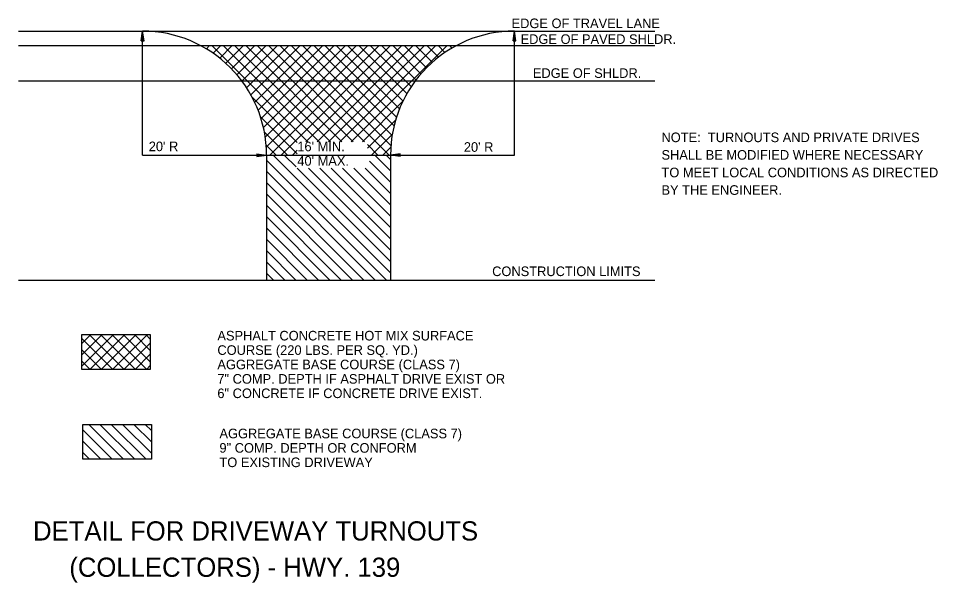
# Model space of a CAD drawing. Extents: x 1955770 to 1955917, y 566446 to 566544.
# Drawn here: x 1955775.3 to 1955832.8, y 566506.6 to 566541.9 of the extents above; entities that cross this region are included whole.
import ezdxf

# ---------------------------------------------------------------- set-up
doc = ezdxf.new("R2010")
doc.units = 0
for name, color, linetype in [('Default', 7, 'Continuous'), ('R_Grid', 7, 'Continuous'), ('R_Logo', 7, 'Continuous')]:
    doc.layers.add(name, color=color, linetype=linetype)

msp = doc.modelspace()

# ---------------------------------------------------------------- linework, layer by layer
at = {"layer": 'R_Grid'}
for p, q in [((1955782.989, 566540.478), (1955783.079, 566541.078)), ((1955782.989, 566540.478), (1955783.079, 566541.078)), ((1955783.169, 566540.478), (1955783.079, 566541.078)), ((1955783.169, 566540.478), (1955783.079, 566541.078)), ((1955806.234, 566540.478), (1955806.324, 566541.078)), ((1955806.234, 566540.478), (1955806.324, 566541.078)), ((1955806.414, 566540.478), (1955806.324, 566541.078)), ((1955806.414, 566540.478), (1955806.324, 566541.078)), ((1955782.989, 566540.478), (1955783.169, 566540.478)), ((1955782.989, 566540.478), (1955783.169, 566540.478)), ((1955783.004, 566540.478), (1955783.079, 566540.978)), ((1955783.004, 566540.478), (1955783.079, 566540.978)), ((1955783.019, 566540.478), (1955783.079, 566540.875)), ((1955783.019, 566540.478), (1955783.079, 566540.875)), ((1955783.034, 566540.478), (1955783.079, 566540.775)), ((1955783.034, 566540.478), (1955783.079, 566540.775)), ((1955783.05, 566540.478), (1955783.079, 566540.673)), ((1955783.05, 566540.478), (1955783.079, 566540.673)), ((1955783.065, 566540.478), (1955783.079, 566540.573)), ((1955783.065, 566540.478), (1955783.079, 566540.573)), ((1955783.154, 566540.478), (1955783.079, 566540.978)), ((1955783.154, 566540.478), (1955783.079, 566540.978)), ((1955783.139, 566540.478), (1955783.079, 566540.875)), ((1955783.139, 566540.478), (1955783.079, 566540.875)), ((1955783.124, 566540.478), (1955783.079, 566540.775)), ((1955783.124, 566540.478), (1955783.079, 566540.775)), ((1955783.109, 566540.478), (1955783.079, 566540.673)), ((1955783.109, 566540.478), (1955783.079, 566540.673)), ((1955783.093, 566540.478), (1955783.079, 566540.573)), ((1955783.093, 566540.478), (1955783.079, 566540.573)), ((1955806.234, 566540.478), (1955806.414, 566540.478)), ((1955806.234, 566540.478), (1955806.414, 566540.478)), ((1955806.249, 566540.478), (1955806.324, 566540.978)), ((1955806.249, 566540.478), (1955806.324, 566540.978)), ((1955806.265, 566540.478), (1955806.324, 566540.875)), ((1955806.265, 566540.478), (1955806.324, 566540.875)), ((1955806.28, 566540.478), (1955806.324, 566540.775)), ((1955806.28, 566540.478), (1955806.324, 566540.775)), ((1955806.295, 566540.478), (1955806.324, 566540.673)), ((1955806.295, 566540.478), (1955806.324, 566540.673)), ((1955806.31, 566540.478), (1955806.324, 566540.573)), ((1955806.31, 566540.478), (1955806.324, 566540.573)), ((1955806.399, 566540.478), (1955806.324, 566540.978)), ((1955806.399, 566540.478), (1955806.324, 566540.978)), ((1955806.384, 566540.478), (1955806.324, 566540.875)), ((1955806.384, 566540.478), (1955806.324, 566540.875)), ((1955806.369, 566540.478), (1955806.324, 566540.775)), ((1955806.369, 566540.478), (1955806.324, 566540.775)), ((1955806.354, 566540.478), (1955806.324, 566540.673)), ((1955806.354, 566540.478), (1955806.324, 566540.673)), ((1955806.338, 566540.478), (1955806.324, 566540.573)), ((1955806.338, 566540.478), (1955806.324, 566540.573)), ((1955790.228, 566533.42), (1955790.828, 566533.33)), ((1955790.228, 566533.42), (1955790.228, 566533.24)), ((1955790.228, 566533.42), (1955790.828, 566533.33)), ((1955790.228, 566533.42), (1955790.228, 566533.24)), ((1955790.228, 566533.405), (1955790.727, 566533.33)), ((1955790.228, 566533.405), (1955790.727, 566533.33)), ((1955790.228, 566533.39), (1955790.624, 566533.33)), ((1955790.228, 566533.39), (1955790.624, 566533.33)), ((1955790.228, 566533.375), (1955790.524, 566533.33)), ((1955790.228, 566533.375), (1955790.524, 566533.33)), ((1955790.228, 566533.359), (1955790.423, 566533.33)), ((1955790.228, 566533.359), (1955790.423, 566533.33)), ((1955790.228, 566533.344), (1955790.322, 566533.33)), ((1955790.228, 566533.344), (1955790.322, 566533.33)), ((1955790.228, 566533.24), (1955790.828, 566533.33)), ((1955790.228, 566533.301), (1955790.423, 566533.33)), ((1955790.228, 566533.27), (1955790.624, 566533.33)), ((1955790.228, 566533.255), (1955790.727, 566533.33)), ((1955790.228, 566533.285), (1955790.524, 566533.33)), ((1955790.228, 566533.316), (1955790.322, 566533.33)), ((1955790.228, 566533.24), (1955790.828, 566533.33)), ((1955790.228, 566533.301), (1955790.423, 566533.33)), ((1955790.228, 566533.27), (1955790.624, 566533.33)), ((1955790.228, 566533.255), (1955790.727, 566533.33)), ((1955790.228, 566533.285), (1955790.524, 566533.33)), ((1955790.228, 566533.316), (1955790.322, 566533.33)), ((1955799.176, 566533.42), (1955798.576, 566533.33)), ((1955799.176, 566533.42), (1955798.576, 566533.33)), ((1955799.176, 566533.24), (1955798.576, 566533.33)), ((1955799.176, 566533.24), (1955798.576, 566533.33)), ((1955799.176, 566533.405), (1955798.676, 566533.33)), ((1955799.176, 566533.405), (1955798.676, 566533.33)), ((1955799.176, 566533.255), (1955798.676, 566533.33)), ((1955799.176, 566533.255), (1955798.676, 566533.33)), ((1955799.176, 566533.39), (1955798.779, 566533.33)), ((1955799.176, 566533.39), (1955798.779, 566533.33)), ((1955799.176, 566533.27), (1955798.779, 566533.33)), ((1955799.176, 566533.27), (1955798.779, 566533.33)), ((1955799.176, 566533.375), (1955798.879, 566533.33)), ((1955799.176, 566533.375), (1955798.879, 566533.33)), ((1955799.176, 566533.285), (1955798.879, 566533.33)), ((1955799.176, 566533.285), (1955798.879, 566533.33)), ((1955799.176, 566533.359), (1955798.981, 566533.33)), ((1955799.176, 566533.359), (1955798.981, 566533.33)), ((1955799.176, 566533.301), (1955798.981, 566533.33)), ((1955799.176, 566533.301), (1955798.981, 566533.33)), ((1955799.176, 566533.344), (1955799.081, 566533.33)), ((1955799.176, 566533.344), (1955799.081, 566533.33)), ((1955799.176, 566533.316), (1955799.081, 566533.33)), ((1955799.176, 566533.316), (1955799.081, 566533.33)), ((1955799.176, 566533.24), (1955799.176, 566533.42)), ((1955799.176, 566533.24), (1955799.176, 566533.42))]:
    msp.add_line(p, q, dxfattribs=at)
at = {"layer": 'R_Logo'}
for p, q in [((1955775.318, 566541.078), (1955815.092, 566541.078)), ((1955783.079, 566533.33), (1955783.079, 566541.078)), ((1955806.324, 566533.33), (1955806.324, 566541.078)), ((1955775.318, 566540.176), (1955815.092, 566540.176)), ((1955787.066, 566539.974), (1955787.268, 566540.176)), ((1955787.41, 566540.176), (1955793.415, 566534.171)), ((1955787.495, 566539.697), (1955787.975, 566540.176)), ((1955787.901, 566539.395), (1955788.682, 566540.176)), ((1955788.117, 566540.176), (1955794.122, 566534.171)), ((1955788.283, 566539.07), (1955789.389, 566540.176)), ((1955788.643, 566538.723), (1955790.096, 566540.176)), ((1955788.824, 566540.176), (1955794.829, 566534.171)), ((1955788.98, 566538.352), (1955790.804, 566540.176)), ((1955789.293, 566537.959), (1955791.511, 566540.176)), ((1955789.531, 566540.176), (1955795.536, 566534.171)), ((1955789.583, 566537.542), (1955792.218, 566540.176)), ((1955789.849, 566537.1), (1955792.925, 566540.176)), ((1955790.088, 566536.633), (1955793.632, 566540.176)), ((1955790.238, 566540.176), (1955796.243, 566534.171)), ((1955790.301, 566536.138), (1955794.339, 566540.176)), ((1955790.483, 566535.614), (1955795.046, 566540.176)), ((1955790.633, 566535.056), (1955795.753, 566540.176)), ((1955790.745, 566534.461), (1955796.46, 566540.176)), ((1955790.812, 566533.821), (1955797.167, 566540.176)), ((1955790.945, 566540.176), (1955796.95, 566534.171)), ((1955791.028, 566533.33), (1955797.875, 566540.176)), ((1955791.652, 566540.176), (1955798.498, 566533.33)), ((1955791.735, 566533.33), (1955798.582, 566540.176)), ((1955792.359, 566540.176), (1955798.6, 566533.936)), ((1955793.066, 566540.176), (1955798.675, 566534.567)), ((1955793.284, 566534.171), (1955799.289, 566540.176)), ((1955793.773, 566540.176), (1955798.794, 566535.156)), ((1955793.991, 566534.171), (1955799.996, 566540.176)), ((1955794.481, 566540.176), (1955798.95, 566535.707)), ((1955794.698, 566534.171), (1955800.703, 566540.176)), ((1955795.188, 566540.176), (1955799.138, 566536.226)), ((1955795.405, 566534.171), (1955801.41, 566540.176)), ((1955795.895, 566540.176), (1955799.355, 566536.716)), ((1955796.112, 566534.171), (1955802.117, 566540.176)), ((1955796.602, 566540.176), (1955799.599, 566537.179)), ((1955797.309, 566540.176), (1955799.869, 566537.616)), ((1955798.016, 566540.176), (1955800.163, 566538.029)), ((1955798.723, 566540.176), (1955800.481, 566538.419)), ((1955799.43, 566540.176), (1955800.822, 566538.785)), ((1955800.137, 566540.176), (1955801.185, 566539.129)), ((1955800.845, 566540.176), (1955801.571, 566539.449)), ((1955801.552, 566540.176), (1955801.981, 566539.747)), ((1955802.259, 566540.176), (1955802.415, 566540.02)), ((1955775.318, 566537.979), (1955815.092, 566537.979)), ((1955789.931, 566536.947), (1955792.751, 566534.128)), ((1955796.819, 566534.171), (1955799.346, 566536.698)), ((1955790.449, 566535.723), (1955792.751, 566533.421)), ((1955797.131, 566533.776), (1955798.899, 566535.544)), ((1955790.692, 566534.772), (1955792.134, 566533.33)), ((1955797.392, 566533.33), (1955798.684, 566534.622)), ((1955790.802, 566533.955), (1955791.427, 566533.33)), ((1955792.443, 566533.33), (1955792.751, 566533.638)), ((1955797.131, 566533.991), (1955797.791, 566533.33)), ((1955798.099, 566533.33), (1955798.592, 566533.822)), ((1955783.079, 566533.33), (1955790.828, 566533.33)), ((1955790.828, 566533.33), (1955790.828, 566525.53)), ((1955790.828, 566533.33), (1955798.576, 566533.33)), ((1955798.325, 566525.53), (1955790.828, 566533.027)), ((1955798.576, 566525.986), (1955791.232, 566533.33)), ((1955792.679, 566532.59), (1955791.939, 566533.33)), ((1955798.576, 566532.35), (1955797.596, 566533.33)), ((1955798.576, 566533.057), (1955798.303, 566533.33)), ((1955798.576, 566533.33), (1955798.576, 566525.53)), ((1955798.576, 566533.33), (1955806.324, 566533.33)), ((1955798.576, 566526.693), (1955792.747, 566532.522)), ((1955798.576, 566527.4), (1955793.454, 566532.522)), ((1955798.576, 566528.107), (1955794.161, 566532.522)), ((1955798.576, 566528.814), (1955794.868, 566532.522)), ((1955798.576, 566529.522), (1955795.576, 566532.522)), ((1955798.576, 566530.229), (1955796.283, 566532.522)), ((1955798.576, 566530.936), (1955796.99, 566532.522)), ((1955798.576, 566531.643), (1955797.264, 566532.955)), ((1955797.618, 566525.53), (1955790.828, 566532.32)), ((1955796.911, 566525.53), (1955790.828, 566531.613)), ((1955796.203, 566525.53), (1955790.828, 566530.906)), ((1955795.496, 566525.53), (1955790.828, 566530.199)), ((1955794.789, 566525.53), (1955790.828, 566529.492)), ((1955794.082, 566525.53), (1955790.828, 566528.785)), ((1955793.375, 566525.53), (1955790.828, 566528.078)), ((1955792.668, 566525.53), (1955790.828, 566527.37)), ((1955791.961, 566525.53), (1955790.828, 566526.663)), ((1955775.318, 566525.53), (1955815.092, 566525.53)), ((1955791.254, 566525.53), (1955790.828, 566525.956)), ((1955779.282, 566521.556), (1955779.852, 566522.125)), ((1955779.282, 566520.848), (1955780.559, 566522.125)), ((1955779.282, 566520.141), (1955781.266, 566522.125)), ((1955781.926, 566519.943), (1955779.744, 566522.125)), ((1955779.791, 566519.943), (1955781.973, 566522.125)), ((1955782.633, 566519.943), (1955780.451, 566522.125)), ((1955780.498, 566519.943), (1955782.68, 566522.125)), ((1955783.34, 566519.943), (1955781.158, 566522.125)), ((1955781.205, 566519.943), (1955783.387, 566522.125)), ((1955783.563, 566520.427), (1955781.865, 566522.125)), ((1955783.563, 566521.134), (1955782.572, 566522.125)), ((1955783.563, 566521.841), (1955783.279, 566522.125)), ((1955781.219, 566519.943), (1955779.282, 566521.879)), ((1955781.912, 566519.943), (1955783.563, 566521.594)), ((1955780.512, 566519.943), (1955779.282, 566521.172)), ((1955779.804, 566519.943), (1955779.282, 566520.465)), ((1955782.62, 566519.943), (1955783.563, 566520.887)), ((1955783.327, 566519.943), (1955783.563, 566520.18)), ((1955781.893, 566514.327), (1955779.711, 566516.509)), ((1955782.6, 566514.327), (1955780.418, 566516.509)), ((1955783.307, 566514.327), (1955781.125, 566516.509)), ((1955783.632, 566514.71), (1955781.832, 566516.509)), ((1955783.632, 566515.417), (1955782.539, 566516.509)), ((1955783.632, 566516.124), (1955783.246, 566516.509)), ((1955781.186, 566514.327), (1955779.351, 566516.162)), ((1955780.479, 566514.327), (1955779.351, 566515.455)), ((1955779.772, 566514.327), (1955779.351, 566514.748))]:
    msp.add_line(p, q, dxfattribs=at)
for points in [[(1955779.282, 566522.125), (1955783.563, 566522.125), (1955783.563, 566519.943), (1955779.282, 566519.943)], [(1955779.351, 566516.509), (1955783.632, 566516.509), (1955783.632, 566514.327), (1955779.351, 566514.327)]]:
    msp.add_lwpolyline(points, close=True, dxfattribs=at)
for centre, start, end in [((1955783.079, 566533.33), 0, 90), ((1955806.324, 566533.33), 90, 180)]:
    msp.add_arc(centre, 7.748, start, end, dxfattribs=at)

# ---------------------------------------------------------------- texts
at = {"layer": 'Default'}
for s, p in [('NOTE:  TURNOUTS AND PRIVATE DRIVES', (1955815.511, 566534.143)), ('SHALL BE MODIFIED WHERE NECESSARY', (1955815.511, 566533.046)), ('TO MEET LOCAL CONDITIONS AS DIRECTED', (1955815.511, 566531.948)), ('BY THE ENGINEER.', (1955815.511, 566530.851))]:
    msp.add_text(s, height=0.6, dxfattribs=at).set_placement(p)
at = {"layer": 'R_Logo'}
for s, height, p in [('EDGE OF TRAVEL LANE', 0.6, (1955806.142, 566541.265)), ('EDGE OF PAVED SHLDR.', 0.6, (1955806.707, 566540.278)), ('EDGE OF SHLDR.', 0.6, (1955807.473, 566538.157)), ("20' R", 0.6, (1955783.466, 566533.577)), ("16' MIN.", 0.6, (1955792.751, 566533.571)), ("20' R", 0.6, (1955803.158, 566533.539)), ("40' MAX.", 0.6, (1955792.751, 566532.671)), ('CONSTRUCTION LIMITS', 0.6, (1955804.929, 566525.774)), ('ASPHALT CONCRETE HOT MIX SURFACE', 0.6, (1955787.755, 566521.752)), ('COURSE (220 LBS. PER SQ. YD.) ', 0.6, (1955787.755, 566520.852)), ('AGGREGATE BASE COURSE (CLASS 7) ', 0.6, (1955787.755, 566519.952)), ('7" COMP. DEPTH IF ASPHALT DRIVE EXIST OR', 0.6, (1955787.755, 566519.052)), ('6" CONCRETE IF CONCRETE DRIVE EXIST.', 0.6, (1955787.755, 566518.152)), ('AGGREGATE BASE COURSE (CLASS 7)', 0.6, (1955787.884, 566515.64)), ('9" COMP. DEPTH OR CONFORM', 0.6, (1955787.884, 566514.74)), ('TO EXISTING DRIVEWAY', 0.6, (1955787.884, 566513.84)), ('DETAIL FOR DRIVEWAY TURNOUTS', 1.2, (1955776.235, 566509.254)), ('(COLLECTORS) - HWY. 139', 1.2, (1955778.502, 566506.986))]:
    msp.add_text(s, height=height, dxfattribs=at).set_placement(p)

doc.saveas('drawing.dxf')
